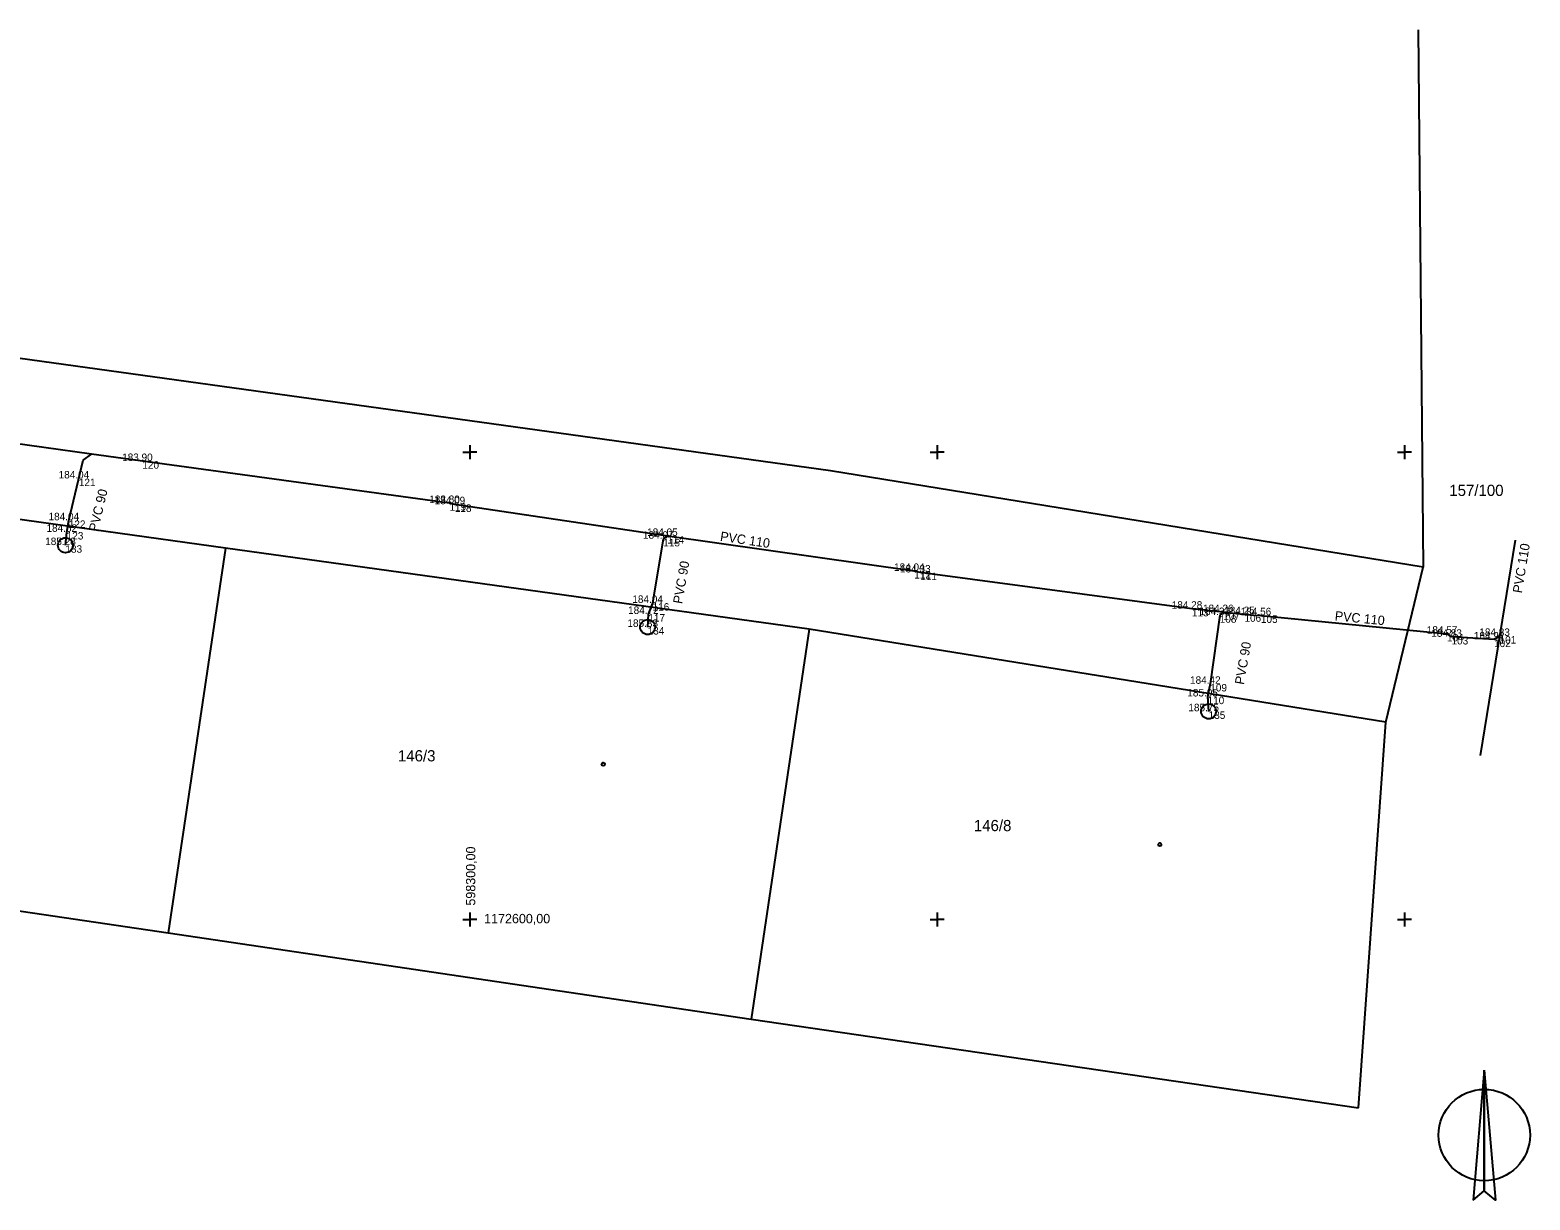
# Model space of a CAD drawing. Extents: x -598400 to -598043, y -1172615 to -1172551.
# Drawn here: x -598323.5 to -598243.3, y -1172615 to -1172552.4 of the extents above; entities that cross this region are included whole.
import ezdxf

# ---------------------------------------------------------------- set-up
doc = ezdxf.new("R2010")
doc.units = 0
for name, color, linetype in [('20', 7, 'Continuous'), ('21', 7, 'Continuous'), ('22', 7, 'Continuous'), ('25', 7, 'Continuous'), ('49', 7, 'Continuous'), ('62', 7, 'Continuous')]:
    doc.layers.add(name, color=color, linetype=linetype)

# ---------------------------------------------------------------- blocks, each defined once
blk = doc.blocks.new('POINT_DISPLAY')
blk.add_line((0, 0), (0, 0))
blk = doc.blocks.new('300')
at = {"layer": '62'}
for p, q in [((-1.5, 0), (0, 0)), ((0, 1.5), (0, -1.5)), ((1.5, 0), (0, 0))]:
    blk.add_line(p, q, dxfattribs=at)
blk = doc.blocks.new('299')
at = {"layer": '62', "xscale": 0.5, "yscale": 0.5}
blk.add_blockref('300', (0, 0), dxfattribs=at)
blk = doc.blocks.new('SEVER')
at = {"layer": '62'}
for p, q in [((0, 6.954), (-1.202, -6.95)), ((0, 6.954), (0, -5.954)), ((-1.202, -6.95), (0, -5.954))]:
    blk.add_line(p, q, dxfattribs=at)
blk.add_lwpolyline([(0, 6.954), (1.202, -6.95), (0, -5.954), (0, 6.954)], close=True, dxfattribs=at)
blk.add_circle((0, 0), 4.89, dxfattribs=at)
blk = doc.blocks.new('6$200')
at = {"layer": '25'}
blk.add_circle((0, 0), 1, dxfattribs=at)
blk = doc.blocks.new('4$020')
at = {"layer": '49'}
blk.add_circle((0, 0), 0.175, dxfattribs=at)

msp = doc.modelspace()

# ---------------------------------------------------------------- linework, layer by layer
at = {"layer": '20'}
for p, q in [((-598249.274, -1172552.419), (-598249.01, -1172581.164)), ((-598280.714, -1172576.008), (-598363.28, -1172564.54)), ((-598249.01, -1172581.164), (-598280.714, -1172576.008)), ((-598284.96, -1172605.33), (-598252.463, -1172610.087))]:
    msp.add_line(p, q, dxfattribs=at)
for points in [[(-598313.07, -1172580.13), (-598338.7, -1172576.57), (-598340.77, -1172576.56), (-598342.58, -1172577.03), (-598344.26, -1172577.94), (-598345.9, -1172579.55), (-598346.76, -1172580.97), (-598347.39, -1172583.13), (-598347.8, -1172586.1), (-598354.04, -1172585.24)], [(-598281.85, -1172584.47), (-598313.07, -1172580.13), (-598316.14, -1172600.72)], [(-598252.463, -1172610.087), (-598251, -1172589.44), (-598249.01, -1172581.164)], [(-598251, -1172589.44), (-598281.85, -1172584.47), (-598284.96, -1172605.33)], [(-598348.93, -1172595.88), (-598316.14, -1172600.72), (-598284.96, -1172605.33)]]:
    msp.add_lwpolyline(points, dxfattribs=at)
at = {"layer": '25'}
for p, q in [((-598320.233, -1172575.115), (-598334.409, -1172573.113)), ((-598320.678, -1172575.438), (-598320.233, -1172575.115)), ((-598301.09, -1172577.733), (-598320.233, -1172575.115)), ((-598321.453, -1172578.656), (-598320.678, -1172575.438)), ((-598300.803, -1172577.798), (-598301.09, -1172577.733)), ((-598289.436, -1172579.493), (-598300.803, -1172577.798)), ((-598321.565, -1172579.275), (-598321.453, -1172578.656)), ((-598321.633, -1172579.983), (-598321.565, -1172579.275)), ((-598289.656, -1172579.644), (-598290.226, -1172583.079)), ((-598289.436, -1172579.493), (-598289.656, -1172579.644)), ((-598276.228, -1172581.365), (-598289.436, -1172579.493)), ((-598244.086, -1172579.706), (-598245.958, -1172591.239)), ((-598275.907, -1172581.448), (-598276.228, -1172581.365)), ((-598261.375, -1172583.387), (-598275.907, -1172581.448)), ((-598290.226, -1172583.079), (-598290.453, -1172583.666)), ((-598290.453, -1172583.666), (-598290.489, -1172584.36)), ((-598259.701, -1172583.569), (-598261.375, -1172583.387)), ((-598259.888, -1172583.726), (-598260.393, -1172587.404)), ((-598259.701, -1172583.569), (-598259.888, -1172583.726)), ((-598259.701, -1172583.569), (-598258.077, -1172583.721)), ((-598258.077, -1172583.721), (-598257.686, -1172583.737)), ((-598257.686, -1172583.737), (-598247.731, -1172584.722)), ((-598247.489, -1172584.89), (-598247.731, -1172584.722)), ((-598245.212, -1172585.03), (-598247.489, -1172584.89)), ((-598244.92, -1172584.843), (-598245.212, -1172585.03)), ((-598260.393, -1172587.404), (-598260.54, -1172588.082)), ((-598260.54, -1172588.082), (-598260.483, -1172588.872))]:
    msp.add_line(p, q, dxfattribs=at)

# ---------------------------------------------------------------- block references
at = {"layer": '22'}
for p in [(-598317.518, -1172575.486), (-598320.914, -1172576.419), (-598301.09, -1172577.733), (-598300.803, -1172577.798), (-598321.453, -1172578.656), (-598321.565, -1172579.275), (-598289.656, -1172579.644), (-598289.436, -1172579.493), (-598321.633, -1172579.983), (-598313.07, -1172580.13), (-598276.228, -1172581.365), (-598275.907, -1172581.448), (-598290.226, -1172583.079), (-598290.453, -1172583.666), (-598261.375, -1172583.387), (-598259.888, -1172583.726), (-598259.701, -1172583.569), (-598258.566, -1172583.675), (-598257.686, -1172583.737), (-598290.489, -1172584.36), (-598281.85, -1172584.47), (-598247.731, -1172584.722), (-598247.489, -1172584.89), (-598245.212, -1172585.03), (-598244.92, -1172584.843), (-598260.393, -1172587.404), (-598260.54, -1172588.082), (-598260.483, -1172588.872), (-598251, -1172589.44), (-598316.14, -1172600.72), (-598284.96, -1172605.33)]:
    msp.add_blockref('POINT_DISPLAY', p, dxfattribs=at)
at = {"layer": '25', "xscale": 0.3999990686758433, "yscale": 0.3999990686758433}
for p in [(-598321.633, -1172579.983), (-598290.489, -1172584.36), (-598260.483, -1172588.872)]:
    msp.add_blockref('6$200', p, dxfattribs=at)
at = {"layer": '49', "xscale": 0.5, "yscale": 0.5}
for p in [(-598292.866, -1172591.7), (-598263.092, -1172595.994)]:
    msp.add_blockref('4$020', p, dxfattribs=at)
at = {"layer": '62', "xscale": 0.5, "yscale": 0.5}
for name, p in [('299', (-598300, -1172575)), ('299', (-598275, -1172575)), ('299', (-598250, -1172575)), ('299', (-598300, -1172600)), ('299', (-598275, -1172600)), ('299', (-598250, -1172600)), ('SEVER', (-598245.737, -1172611.534))]:
    msp.add_blockref(name, p, dxfattribs=at)

# ---------------------------------------------------------------- texts
at = {"layer": '20'}
for s, height, p in [('120', 0.4, (-598317.518, -1172575.886)), ('121', 0.4, (-598320.914, -1172576.819)), ('157/100', 0.6, (-598247.608, -1172577.344)), ('119', 0.4, (-598301.09, -1172578.133)), ('118', 0.4, (-598300.803, -1172578.198)), ('122', 0.4, (-598321.453, -1172579.056)), ('123', 0.4, (-598321.565, -1172579.675)), ('115', 0.4, (-598289.656, -1172580.044)), ('114', 0.4, (-598289.436, -1172579.893)), ('133', 0.4, (-598321.633, -1172580.383)), ('112', 0.4, (-598276.228, -1172581.765)), ('111', 0.4, (-598275.907, -1172581.848)), ('116', 0.4, (-598290.226, -1172583.479)), ('117', 0.4, (-598290.453, -1172584.066)), ('113', 0.4, (-598261.375, -1172583.787)), ('108', 0.4, (-598259.888, -1172584.126)), ('107', 0.4, (-598259.701, -1172583.969)), ('106', 0.4, (-598258.566, -1172584.075)), ('105', 0.4, (-598257.686, -1172584.137)), ('134', 0.4, (-598290.489, -1172584.76)), ('104', 0.4, (-598247.731, -1172585.122)), ('103', 0.4, (-598247.489, -1172585.29)), ('102', 0.4, (-598245.212, -1172585.43)), ('101', 0.4, (-598244.92, -1172585.243)), ('109', 0.4, (-598260.393, -1172587.804)), ('110', 0.4, (-598260.54, -1172588.482)), ('135', 0.4, (-598260.483, -1172589.272)), ('146/3', 0.6, (-598303.846, -1172591.545)), ('146/8', 0.6, (-598273.039, -1172595.278))]:
    msp.add_text(s, height=height, dxfattribs=at).set_placement(p)
at = {"layer": '21'}
for s, p in [('183.90', (-598318.601, -1172575.476)), ('184.04', (-598321.997, -1172576.409)), ('183.80', (-598302.173, -1172577.723)), ('184.09', (-598301.886, -1172577.788)), ('184.04', (-598322.536, -1172578.646)), ('184.62', (-598322.648, -1172579.265)), ('184.05', (-598290.519, -1172579.483)), ('185.28', (-598322.716, -1172579.973)), ('184.07', (-598290.739, -1172579.634)), ('184.04', (-598277.311, -1172581.355)), ('184.33', (-598276.99, -1172581.438)), ('184.04', (-598291.309, -1172583.069)), ('184.28', (-598262.458, -1172583.377)), ('184.26', (-598260.784, -1172583.559)), ('185.33', (-598291.572, -1172584.35)), ('184.72', (-598291.536, -1172583.656)), ('184.33', (-598260.971, -1172583.716)), ('184.25', (-598259.649, -1172583.665)), ('184.56', (-598258.769, -1172583.727)), ('184.57', (-598248.814, -1172584.712)), ('184.83', (-598248.572, -1172584.88)), ('184.91', (-598246.295, -1172585.02)), ('184.83', (-598246.003, -1172584.833)), ('184.42', (-598261.476, -1172587.394)), ('185.05', (-598261.623, -1172588.072)), ('185.75', (-598261.566, -1172588.862))]:
    msp.add_text(s, height=0.4, dxfattribs=at).set_placement(p)
at = {"layer": '25'}
for s, rotation, p in [('PVC 90', 76.49783, (-598319.906, -1172579.286)), ('PVC 110', 351.55271, (-598286.635, -1172579.739)), ('PVC 110', 80.66881, (-598243.728, -1172582.57)), ('PVC 90', 80.18951, (-598288.645, -1172583.144)), ('PVC 110', 354.37729, (-598253.752, -1172584.001)), ('PVC 90', 80.18951, (-598258.595, -1172587.466))]:
    msp.add_text(s, height=0.5, rotation=rotation, dxfattribs=at).set_placement(p)
at = {"layer": '62'}
msp.add_text('598300,00', height=0.5, rotation=90, dxfattribs=at).set_placement((-598299.708, -1172599.26))
msp.add_text('1172600,00', height=0.5, dxfattribs=at).set_placement((-598299.235, -1172600.204))

doc.saveas('drawing.dxf')
